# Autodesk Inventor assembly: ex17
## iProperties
Shininess: 64.0
Length Units: 11272
Angle Units: 11279
Time Units: 11290
Mass Units: 11286
Length Display Precision: 3
Angle Display Precision: 2
Compacted: True
Part Number: ex17
Document SubType Name: Assembly
Created: 2002-11
Designer: E. MOSS
Density: 0.0
Volumn: 0.0
Area: 0.0
PropertySet Name: Model Information
Control State: 0
Master: False
Checked Out: False
Author: E. MOSS
